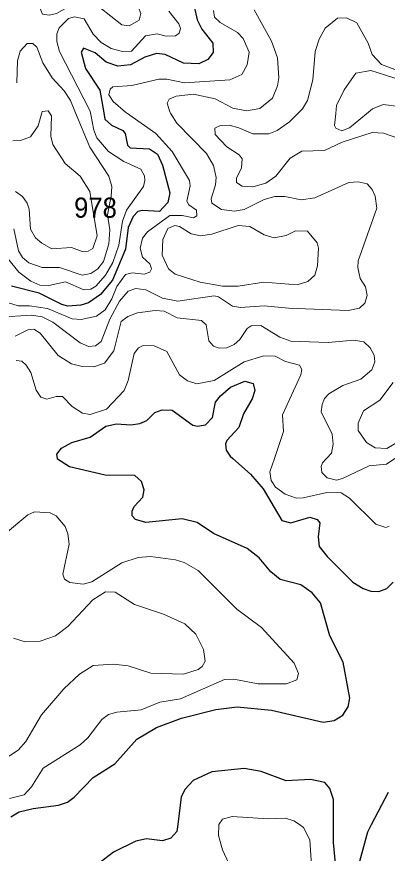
# Model space of a CAD drawing. Extents: x 473.9 to 500, y 7733.1 to 7760.8.
# Drawn here: x 489.935 to 491.405, y 7743.401 to 7746.72 of the extents above; entities that cross this region are included whole.
import ezdxf

# ---------------------------------------------------------------- set-up
doc = ezdxf.new("R2010")
doc.units = 0
doc.header["$LTSCALE"] = 0.032
doc.layers.add('1', color=7, linetype='Continuous', lineweight=25)
doc.layers.add('2', color=7, linetype='Continuous', lineweight=13)
doc.layers.add('21', color=7, linetype='Continuous')

msp = doc.modelspace()

# ---------------------------------------------------------------- linework, layer by layer
at = {"layer": '1'}
for points in [[(490.6361, 7746.7719), (490.6509, 7746.7069), (490.6703, 7746.6706), (490.7135, 7746.6141), (490.7148, 7746.5782), (490.693, 7746.5493), (490.6573, 7746.5332), (490.5968, 7746.5353), (490.5237, 7746.5697), (490.4894, 7746.5744), (490.4434, 7746.5591), (490.3872, 7746.5282), (490.337, 7746.524), (490.2905, 7746.5396)], [(490.2905, 7746.5396), (490.2469, 7746.5759), (490.1997, 7746.5949), (490.191, 7746.5796), (490.2083, 7746.5147), (490.2653, 7746.428), (490.2803, 7746.3382), (490.2844, 7746.3138), (490.3112, 7746.2898), (490.3567, 7746.2682), (490.3655, 7746.257), (490.3743, 7746.2102), (490.3858, 7746.2001), (490.4617, 7746.1956), (490.4941, 7746.1741), (490.5134, 7746.1309), (490.5426, 7746.0208), (490.5349, 7745.9828), (490.5012, 7745.9467), (490.4347, 7745.9516), (490.4153, 7745.9467), (490.3969, 7745.9274), (490.377, 7745.8839), (490.3665, 7745.7971), (490.3152, 7745.6744), (490.267, 7745.6176), (490.22, 7745.5841), (490.19, 7745.5749), (490.1385, 7745.5721), (490.1144, 7745.5784), (490.0241, 7745.6229), (489.9145, 7745.6506)], [(490.4017, 7744.7773), (490.4361, 7744.8144), (490.4415, 7744.8431), (490.4301, 7744.8761), (490.4032, 7744.8999), (490.2859, 7744.9008), (490.1444, 7744.9346), (490.0968, 7744.9641), (490.0964, 7744.9675), (490.0944, 7744.9839), (490.113, 7745.0087), (490.1542, 7745.0309), (490.226, 7745.0524), (490.2888, 7745.0956), (490.3309, 7745.1044), (490.3877, 7745.1013), (490.4235, 7745.1057), (490.4519, 7745.1183), (490.4829, 7745.1494), (490.5118, 7745.1603), (490.5523, 7745.1584), (490.6339, 7745.0992), (490.6525, 7745.095), (490.6845, 7745.1012), (490.7125, 7745.1305), (490.7243, 7745.1908), (490.7432, 7745.2164), (490.784, 7745.2503), (490.8399, 7745.274), (490.8731, 7745.2648), (490.8803, 7745.2373), (490.8694, 7745.2033), (490.8355, 7745.1448), (490.816, 7745.0906), (490.769, 7745.0384), (490.7637, 7745.0253), (490.766, 7745.0002), (490.7824, 7744.9766), (490.7925, 7744.9675), (490.8623, 7744.9048), (490.9126, 7744.8473), (490.9871, 7744.7208), (491.023, 7744.7123), (491.0985, 7744.7347), (491.1276, 7744.7256), (491.1374, 7744.7122), (491.1306, 7744.6564), (491.1354, 7744.6179), (491.1665, 7744.579), (491.2683, 7744.4771), (491.3104, 7744.4515), (491.3407, 7744.4417), (491.372, 7744.4402), (491.4034, 7744.4516), (491.4292, 7744.4774)], [(489.9125, 7743.5463), (489.9449, 7743.5655), (490.0003, 7743.5792), (490.1013, 7743.592), (490.1373, 7743.6046), (490.1637, 7743.624), (490.2381, 7743.7023), (490.3241, 7743.7563), (490.4113, 7743.8539), (490.49, 7743.8998), (490.5895, 7743.9378), (490.7255, 7743.9716), (490.8105, 7743.9822), (490.9454, 7743.9692), (491.151, 7743.9212), (491.1944, 7743.9279), (491.2295, 7743.9495), (491.2508, 7743.9816), (491.2568, 7744.0163), (491.2302, 7744.159), (491.178, 7744.2635), (491.1408, 7744.3952), (491.1079, 7744.4339), (491.0622, 7744.4662), (490.9802, 7744.4874), (490.9438, 7744.518), (490.8965, 7744.5739), (490.8494, 7744.6097), (490.7154, 7744.6702), (490.6505, 7744.7136), (490.591, 7744.7283), (490.4475, 7744.7133), (490.4068, 7744.7248), (490.3936, 7744.7401), (490.3934, 7744.7587), (490.4017, 7744.7773)], [(491.2005, 7743.3612), (491.1917, 7743.4447), (491.192, 7743.5149), (491.1925, 7743.6142), (491.1771, 7743.6589), (491.1582, 7743.6817), (491.1004, 7743.6943), (491.0043, 7743.6884), (490.905, 7743.7252), (490.8379, 7743.737), (490.7088, 7743.7245), (490.635, 7743.6899), (490.6036, 7743.6559), (490.5881, 7743.6258)], [(490.5881, 7743.6258), (490.5738, 7743.5158), (490.5702, 7743.4878), (490.547, 7743.4617), (490.5135, 7743.4509), (490.4496, 7743.4587), (490.408, 7743.449), (490.3187, 7743.4062), (490.2671, 7743.3663)], [(491.409, 7743.6419), (491.342, 7743.5147), (491.3263, 7743.4848), (491.2954, 7743.3689)]]:
    msp.add_lwpolyline(points, dxfattribs=at)
at = {"layer": '2'}
for points in [[(490.3525, 7746.6869), (490.382, 7746.6829), (490.4208, 7746.7061), (490.427, 7746.7327), (490.4187, 7746.7566), (490.4029, 7746.776), (490.3483, 7746.8019), (490.107, 7746.8357), (490.0534, 7746.8266), (490.034, 7746.809), (490.0243, 7746.7609), (490.0374, 7746.7304), (490.0636, 7746.7263), (490.0924, 7746.7323), (490.1657, 7746.7735), (490.2022, 7746.7809), (490.2651, 7746.7564)], [(490.5378, 7745.7198), (490.5118, 7745.7734), (490.5147, 7745.8362), (490.5349, 7745.8795), (490.5621, 7745.8917), (490.5808, 7745.8872), (490.6275, 7745.859), (490.664, 7745.85), (490.709, 7745.8565), (490.8135, 7745.8909), (490.8607, 7745.887), (490.9169, 7745.8542), (490.9561, 7745.8427), (491.0038, 7745.8514), (491.0415, 7745.871), (491.0888, 7745.8685), (491.1275, 7745.8228), (491.1322, 7745.802), (491.1289, 7745.7318), (491.1175, 7745.6947), (491.09, 7745.6693), (491.0483, 7745.6568), (490.9153, 7745.6667), (490.8134, 7745.6504), (490.7518, 7745.6506), (490.6624, 7745.6661), (490.5635, 7745.6985)]]:
    msp.add_lwpolyline(points, close=True, dxfattribs=at)
for points in [[(489.8267, 7745.8491), (489.9439, 7745.706), (489.9909, 7745.6713), (490.0269, 7745.655), (490.0627, 7745.653), (490.1281, 7745.6683), (490.2018, 7745.6369), (490.2289, 7745.6393), (490.2491, 7745.6503), (490.2875, 7745.6942), (490.317, 7745.7452), (490.3406, 7745.8138), (490.355, 7745.9084), (490.3708, 7745.952), (490.4376, 7746.0459), (490.4439, 7746.0694), (490.4416, 7746.0888), (490.4276, 7746.1143), (490.3601, 7746.1447), (490.2997, 7746.1855), (490.2536, 7746.2397), (490.241, 7746.2699), (490.2277, 7746.3383), (490.2259, 7746.3477), (490.1045, 7746.5811), (490.0942, 7746.6209), (490.0948, 7746.6521), (490.1033, 7746.6762), (490.1406, 7746.7126), (490.1649, 7746.7197), (490.2034, 7746.7109), (490.239, 7746.6502), (490.2696, 7746.6179), (490.3096, 7746.5938), (490.3546, 7746.5818), (490.39, 7746.5836), (490.4457, 7746.6444), (490.4924, 7746.6523), (490.5288, 7746.6422), (490.5653, 7746.6436), (490.5799, 7746.6538), (490.5851, 7746.6734), (490.5781, 7746.6915), (490.539, 7746.7417)], [(489.8642, 7745.5284), (489.9944, 7745.5355), (490.0363, 7745.5296), (490.079, 7745.5084), (490.1873, 7745.4261), (490.2197, 7745.4118), (490.2474, 7745.4144), (490.2697, 7745.432), (490.3052, 7745.52), (490.3425, 7745.592), (490.3772, 7745.6304), (490.408, 7745.6419), (490.4479, 7745.636), (490.5133, 7745.6036), (490.5738, 7745.5912), (490.7187, 7745.613), (490.7359, 7745.608), (490.7915, 7745.5721), (490.8232, 7745.5662), (490.9164, 7745.5734), (491.0139, 7745.5637), (491.2508, 7745.5541), (491.2947, 7745.5641), (491.3159, 7745.5833), (491.326, 7745.6133), (491.3185, 7745.6481), (491.2978, 7745.6808), (491.288, 7745.7249), (491.2894, 7745.7509), (491.3637, 7745.9606), (491.3572, 7746.0083), (491.3449, 7746.0345), (491.3255, 7746.0564), (491.2894, 7746.0646), (491.2524, 7746.0621), (491.1182, 7746.0017), (491.0638, 7745.9931), (490.9989, 7746.0068), (490.9592, 7746.0059), (490.9175, 7745.9947), (490.8376, 7745.9555), (490.7996, 7745.9482), (490.7471, 7745.9554), (490.709, 7745.9797), (490.7067, 7745.9975), (490.7241, 7746.0532), (490.7268, 7746.0822), (490.7158, 7746.1299), (490.6879, 7746.1769), (490.571, 7746.2974), (490.5454, 7746.3374), (490.5423, 7746.3423), (490.5326, 7746.3772), (490.5403, 7746.3931), (490.5683, 7746.4049), (490.637, 7746.412), (490.7229, 7746.3941), (490.7929, 7746.3563), (490.8467, 7746.3469), (490.8997, 7746.3557), (490.9495, 7746.3969), (490.9697, 7746.4457), (490.9754, 7746.4768), (490.9695, 7746.5562), (490.9456, 7746.6225), (490.8777, 7746.7465)], [(490.7157, 7746.7437), (490.7203, 7746.7182), (490.742, 7746.6967), (490.8113, 7746.6571), (490.8343, 7746.6327), (490.8569, 7746.5786), (490.8491, 7746.5293), (490.829, 7746.49), (490.7814, 7746.4697), (490.6003, 7746.4569), (490.531, 7746.4714), (490.4988, 7746.4714), (490.3921, 7746.4464), (490.3166, 7746.4415), (490.3056, 7746.4317), (490.3008, 7746.41), (490.3172, 7746.3834), (490.3671, 7746.3404), (490.3706, 7746.3379), (490.4869, 7746.2562), (490.5526, 7746.1846), (490.6211, 7746.0697), (490.6239, 7746.0486), (490.6097, 7745.9885), (490.6185, 7745.9735), (490.6488, 7745.9527), (490.6499, 7745.9304), (490.6364, 7745.9222), (490.5921, 7745.9312), (490.5422, 7745.9316), (490.4536, 7745.8667), (490.4338, 7745.8417), (490.4247, 7745.8014), (490.4338, 7745.7664), (490.4639, 7745.74), (490.4696, 7745.7193), (490.4635, 7745.7065), (490.4414, 7745.6988), (490.3927, 7745.7034), (490.3672, 7745.6965), (490.3322, 7745.6497), (490.313, 7745.6004), (490.2855, 7745.5565), (490.2511, 7745.5321), (490.1911, 7745.5186), (490.1547, 7745.5217), (490.0577, 7745.5619), (489.9859, 7745.5731), (489.9409, 7745.5735), (489.9022, 7745.5844)], [(491.4462, 7746.5069), (491.3827, 7746.5306), (491.3453, 7746.57), (491.3297, 7746.615), (491.2841, 7746.6949), (491.2439, 7746.7154), (491.208, 7746.7142), (491.1587, 7746.6748), (491.1356, 7746.6312), (491.1192, 7746.5818), (491.1106, 7746.4698), (491.0895, 7746.3879), (491.0694, 7746.3548), (491.0505, 7746.3359), (491.0179, 7746.3033), (490.9679, 7746.2684), (490.9357, 7746.2549), (490.8719, 7746.2546), (490.8167, 7746.279), (490.7776, 7746.2889), (490.7438, 7746.2885), (490.7213, 7746.2772), (490.7226, 7746.2522), (490.7691, 7746.2032), (490.8177, 7746.1715), (490.8301, 7746.1553), (490.827, 7746.1209), (490.8074, 7746.0789), (490.8069, 7746.0627), (490.8303, 7746.0471), (490.8719, 7746.0445), (490.924, 7746.0589), (490.9637, 7746.0868), (491.0199, 7746.1581), (491.0665, 7746.1858), (491.1565, 7746.1887), (491.226, 7746.2214), (491.3458, 7746.26), (491.3902, 7746.2583), (491.4636, 7746.232)], [(489.9234, 7745.8781), (489.9427, 7745.7904), (489.9585, 7745.7652), (489.9835, 7745.7432), (490.0357, 7745.7252), (490.1055, 7745.7243), (490.1954, 7745.694), (490.2287, 7745.701), (490.2573, 7745.7198), (490.2792, 7745.7492), (490.3009, 7745.8185), (490.304, 7745.8738), (490.2959, 7745.9332), (490.3104, 7746.0078), (490.3121, 7746.0463), (490.3012, 7746.0876), (490.2255, 7746.2022), (490.1685, 7746.3385), (490.148, 7746.3875), (490.1232, 7746.4257), (490.0764, 7746.4774), (490.0394, 7746.5372), (490.0145, 7746.5984), (489.999, 7746.6139), (489.9762, 7746.6131), (489.9495, 7746.5825), (489.9388, 7746.5444), (489.9351, 7746.4575)], [(491.4599, 7746.4674), (491.3398, 7746.506), (491.2813, 7746.4957), (491.2344, 7746.4302), (491.2043, 7746.3669), (491.2009, 7746.3354), (491.1958, 7746.2877), (491.2007, 7746.2776), (491.2246, 7746.2664), (491.2554, 7746.2785), (491.3228, 7746.335), (491.3463, 7746.3547), (491.3892, 7746.3709), (491.4519, 7746.3632)], [(489.9302, 7746.0265), (489.9578, 7746.0063), (489.9769, 7745.9803), (489.9844, 7745.9568), (489.9903, 7745.8766), (490.0101, 7745.843), (490.0348, 7745.8208), (490.074, 7745.7995), (490.152, 7745.8043), (490.1952, 7745.7887), (490.2191, 7745.7894), (490.2371, 7745.7998), (490.2549, 7745.8502), (490.2259, 7746.0261), (490.1874, 7746.0871), (490.1272, 7746.1378), (490.0787, 7746.2132), (490.0709, 7746.2453), (490.0732, 7746.3266), (490.0651, 7746.3388), (490.0602, 7746.3463), (490.0356, 7746.3443), (490.0342, 7746.3389), (490.0201, 7746.2864), (489.9897, 7746.2438), (489.9505, 7746.2285), (489.9199, 7746.2277)], [(490.5712, 7745.5255), (490.5198, 7745.5515), (490.4843, 7745.5547), (490.4141, 7745.5452), (490.3761, 7745.5302), (490.3495, 7745.5103), (490.3206, 7745.3937), (490.2837, 7745.346), (490.2405, 7745.3314), (490.1949, 7745.3323), (490.1522, 7745.3428), (490.0995, 7745.3759), (490.0283, 7745.4639), (490.0033, 7745.4798), (489.9793, 7745.478), (489.9294, 7745.4529)], [(491.4359, 7744.9675), (491.4028, 7744.9444), (491.3329, 7744.9382), (491.2274, 7744.8873), (491.2043, 7744.882), (491.167, 7744.8903), (491.1459, 7744.9122), (491.1435, 7744.9354), (491.1489, 7744.9496), (491.1649, 7744.9675), (491.1835, 7744.9882), (491.1909, 7745.0243), (491.1868, 7745.0644), (491.1435, 7745.1527), (491.1465, 7745.1813), (491.157, 7745.2054), (491.174, 7745.2244), (491.2289, 7745.257), (491.3011, 7745.2826), (491.3438, 7745.319), (491.3559, 7745.3513), (491.353, 7745.3772), (491.3378, 7745.4069), (491.3125, 7745.4296), (491.2728, 7745.4366), (491.1709, 7745.4271), (491.0223, 7745.4333), (490.9786, 7745.4488), (490.9043, 7745.4942), (490.8655, 7745.4937), (490.85, 7745.4831), (490.8209, 7745.4392), (490.7976, 7745.419), (490.7693, 7745.4068), (490.7385, 7745.4052), (490.7164, 7745.4127), (490.6974, 7745.434), (490.6866, 7745.4974), (490.6685, 7745.5147), (490.5712, 7745.5255)], [(490.5805, 7745.2993), (490.5307, 7745.3912), (490.4801, 7745.4141), (490.4371, 7745.4155), (490.4181, 7745.4061), (490.4017, 7745.3836), (490.3777, 7745.2761), (490.3611, 7745.2371), (490.2916, 7745.1629), (490.2272, 7745.1416), (490.1965, 7745.1467), (490.1548, 7745.1739), (490.1174, 7745.2136), (490.0915, 7745.2132), (490.0541, 7745.2021), (490.0309, 7745.2103), (490.0122, 7745.2378), (489.9914, 7745.308), (489.9732, 7745.3381), (489.9553, 7745.3535), (489.9324, 7745.3556)], [(491.4135, 7744.6987), (491.4003, 7744.694), (491.3602, 7744.7069), (491.2559, 7744.8095), (491.223, 7744.8311), (491.1651, 7744.8328), (491.0717, 7744.8108), (491.0446, 7744.8104), (490.9999, 7744.8253), (490.9616, 7744.8539), (490.9442, 7744.8795), (490.9392, 7744.9145), (490.9574, 7744.9675), (490.9939, 7745.0738), (490.9898, 7745.1409), (491.0626, 7745.2992), (491.0662, 7745.3208), (491.0576, 7745.337), (491.0011, 7745.3524), (490.9608, 7745.3736), (490.9153, 7745.3746), (490.8375, 7745.3501), (490.7186, 7745.2769), (490.65, 7745.263), (490.6125, 7745.2748), (490.5805, 7745.2993)], [(491.4289, 7745.2685), (491.3756, 7745.1993), (491.3111, 7745.156), (491.2903, 7745.108), (491.2898, 7745.0777), (491.323, 7745.0305), (491.358, 7745.009), (491.4036, 7745.0076), (491.4691, 7745.0459)], [(489.883, 7744.6631), (489.9796, 7744.7439), (490.0052, 7744.7554), (490.0684, 7744.7516), (490.0916, 7744.7401), (490.1272, 7744.6976), (490.1384, 7744.6683), (490.1432, 7744.6281), (490.1175, 7744.508), (490.1243, 7744.489), (490.1457, 7744.4751), (490.1992, 7744.4686), (490.2335, 7744.4781), (490.3517, 7744.5535), (490.4168, 7744.5746), (490.4656, 7744.5779), (490.5649, 7744.5652), (490.5996, 7744.5551), (490.6552, 7744.5224), (490.8081, 7744.37), (490.9063, 7744.2973), (491.0363, 7744.1558), (491.0533, 7744.1141), (491.0463, 7744.0897), (491.0059, 7744.0731), (490.8933, 7744.0731), (490.7968, 7744.0923), (490.7599, 7744.0903), (490.5846, 7744.0144), (490.5031, 7744.0012), (490.4291, 7743.9704), (490.3327, 7743.9605), (490.2995, 7743.9513), (490.273, 7743.9319), (490.2172, 7743.8593), (490.1875, 7743.8316), (490.0396, 7743.7385), (489.9933, 7743.665), (489.9643, 7743.6331), (489.9071, 7743.6181)], [(489.923, 7744.255), (489.9687, 7744.2403), (490.0277, 7744.2427), (490.0892, 7744.2635), (490.1379, 7744.301), (490.237, 7744.4068), (490.288, 7744.439), (490.3252, 7744.4367), (490.4024, 7744.3886), (490.5176, 7744.3494), (490.6024, 7744.3121), (490.6458, 7744.271), (490.6757, 7744.2094), (490.6827, 7744.163), (490.6706, 7744.1421), (490.6548, 7744.1299), (490.5964, 7744.1117), (490.4674, 7744.1163), (490.3772, 7744.1445), (490.3177, 7744.1511), (490.2388, 7744.1462), (490.184, 7744.1122), (490.1223, 7744.0537), (490.0335, 7743.95), (489.9717, 7743.8452), (489.9405, 7743.81), (489.8799, 7743.7709)], [(490.7765, 7743.3604), (490.7513, 7743.4156), (490.7358, 7743.4719), (490.7365, 7743.5139), (490.7377, 7743.5156), (490.7522, 7743.5365), (490.7894, 7743.5472), (490.9324, 7743.5384), (491.0016, 7743.5408), (491.0348, 7743.5303), (491.057, 7743.5151), (491.073, 7743.5042), (491.0984, 7743.4542), (491.1049, 7743.3529)]]:
    msp.add_lwpolyline(points, dxfattribs=at)

# ---------------------------------------------------------------- texts
at = {"layer": '21', "width": 0.95}
msp.add_text('978', height=0.08, dxfattribs=at).set_placement((490.1629, 7745.9223))

doc.saveas('drawing.dxf')
